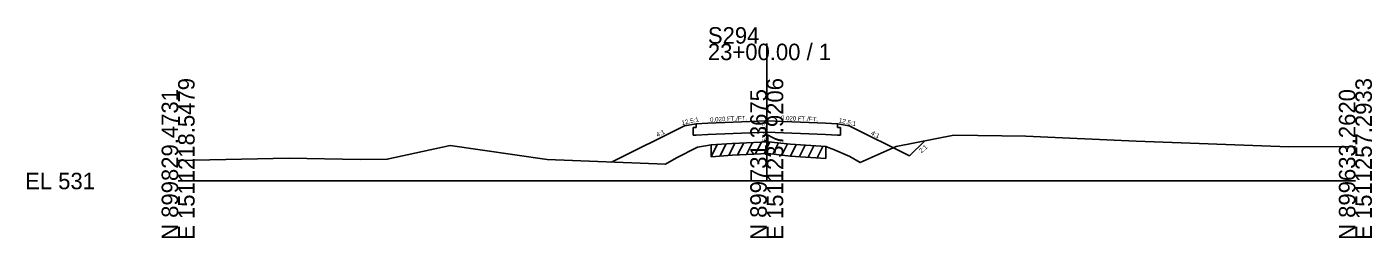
# Model space of a CAD drawing. Extents: x 974 to 2203, y -10 to 19041.
# Drawn here: x 1974.3 to 2202.8, y 5990.3 to 6026.2 of the extents above; entities that cross this region are included whole.
import ezdxf

# ---------------------------------------------------------------- set-up
doc = ezdxf.new("R2010")
doc.units = 0
for name, color, linetype in [('RD_GPK_XS_Cell', 7, 'Continuous'), ('RD_XS_Base', 7, 'Continuous'), ('RD_XS_EarthShd', 7, 'Continuous'), ('RD_XS_ExGround', 7, 'Continuous'), ('RD_XS_ExPaveRet', 7, 'Continuous'), ('RD_XS_Pave', 7, 'Continuous'), ('RD_XS_TX_Elev_EX', 7, 'Continuous'), ('RD_XS_TX_Slope', 7, 'Continuous')]:
    doc.layers.add(name, color=color, linetype=linetype)

msp = doc.modelspace()

# ---------------------------------------------------------------- linework, layer by layer
at = {"layer": 'RD_GPK_XS_Cell'}
for p, q in [((2100, 6000), (2100, 6023.32)), ((2000, 6000), (2100, 6000)), ((2100, 6000), (2200, 6000))]:
    msp.add_line(p, q, dxfattribs=at)
at = {"layer": 'RD_XS_Base'}
for p, q in [((2088, 6009.08), (2087.48, 6009.06)), ((2087.48, 6007.79), (2087.48, 6009.06)), ((2088, 6009.08), (2088, 6009.72)), ((2090, 6007.89), (2100, 6008.29)), ((2110, 6007.89), (2100, 6008.29)), ((2112, 6009.08), (2112, 6009.72)), ((2112, 6009.08), (2112.52, 6009.06)), ((2112.52, 6007.79), (2112.52, 6009.06)), ((2087.98, 6007.81), (2087.48, 6007.79)), ((2087.98, 6007.81), (2090, 6007.89)), ((2112.02, 6007.81), (2110, 6007.89)), ((2112.02, 6007.81), (2112.52, 6007.79))]:
    msp.add_line(p, q, dxfattribs=at)
at = {"layer": 'RD_XS_EarthShd'}
for p, q in [((2086, 6009.39), (2073.6, 6003.19)), ((2088, 6009.72), (2086, 6009.39)), ((2112, 6009.72), (2114, 6009.39)), ((2114, 6009.39), (2124.26, 6004.26)), ((2124.26, 6004.26), (2126.79, 6006.79))]:
    msp.add_line(p, q, dxfattribs=at)
at = {"layer": 'RD_XS_ExGround'}
msp.add_lwpolyline([(2000, 6003.46), (2018.84, 6003.85), (2030.91, 6003.65), (2035.53, 6003.68), (2046.24, 6006.01), (2062.67, 6003.63), (2082.77, 6002.83), (2084.66, 6003.95), (2088.25, 6005.76), (2089.59, 6005.95), (2090.55, 6006.12), (2094.15, 6006.38), (2100.25, 6006.67), (2104.01, 6006.24), (2110.06, 6005.83), (2110.91, 6005.53), (2111.24, 6005.43), (2114.11, 6004.15), (2115.85, 6003.12), (2121.99, 6005.85), (2131.78, 6007.77), (2144.01, 6007.64), (2162.74, 6006.75), (2188.69, 6005.81), (2200, 6005.88)], dxfattribs=at)
at = {"layer": 'RD_XS_ExPaveRet'}
for p, q in [((2090.55, 6004.12), (2091.59, 6006.19)), ((2090.55, 6004.12), (2090.55, 6006.12)), ((2092.05, 6004.23), (2093.09, 6006.3)), ((2093.55, 6004.33), (2094.58, 6006.4)), ((2095.05, 6004.42), (2096.08, 6006.47)), ((2096.55, 6004.49), (2097.58, 6006.54)), ((2098.05, 6004.56), (2099.08, 6006.61)), ((2099.55, 6004.63), (2100.55, 6006.63)), ((2101.05, 6004.58), (2102, 6006.47)), ((2102.55, 6004.41), (2103.5, 6006.3)), ((2104.05, 6004.24), (2105.02, 6006.18)), ((2105.55, 6004.14), (2106.52, 6006.07)), ((2107.05, 6004.04), (2108.02, 6005.97)), ((2108.55, 6003.93), (2109.52, 6005.87)), ((2090.55, 6004.12), (2094.15, 6004.38)), ((2094.15, 6004.38), (2100.25, 6004.67)), ((2100.25, 6004.67), (2104.01, 6004.24)), ((2104.01, 6004.24), (2110.06, 6003.83)), ((2110.06, 6005.83), (2110.06, 6003.83))]:
    msp.add_line(p, q, dxfattribs=at)
at = {"layer": 'RD_XS_Pave'}
for p, q in [((2088, 6009.72), (2090, 6009.8)), ((2090, 6009.8), (2100, 6010.2)), ((2110, 6009.8), (2100, 6010.2)), ((2112, 6009.72), (2110, 6009.8))]:
    msp.add_line(p, q, dxfattribs=at)

# ---------------------------------------------------------------- texts
at = {"layer": 'RD_GPK_XS_Cell'}
for s, p in [('S294', (2090, 6023.32)), ('23+00.00 / 1', (2090, 6020.52)), ('EL 531', (1974, 5998.6))]:
    msp.add_text(s, height=2.8, dxfattribs=at).set_placement(p)
for s, p in [('E 1511218.5479', (2002.8, 5990)), ('E 1511237.9206', (2102.8, 5990)), ('E 1511257.2933', (2202.8, 5990)), ('N 899829.4731', (2000, 5990)), ('N 899731.3675', (2100, 5990)), ('N 899633.2620', (2200, 5990))]:
    msp.add_text(s, height=2.8, rotation=90, dxfattribs=at).set_placement(p)
at = {"layer": 'RD_XS_TX_Elev_EX'}
msp.add_text('534.33', height=0.75, rotation=90, dxfattribs=at).set_placement((2100, 6006.66))
at = {"layer": 'RD_XS_TX_Slope'}
for s, height, rotation, p in [('12.5:1', 0.778, 12.7511, (2085.61, 6009.47)), ('0.020 FT./FT.', 0.7518, 2.396, (2090.38, 6010.06)), ('0.020 FT./FT.', 0.7518, 357.604, (2102.4, 6010.36)), ('12.5:1', 0.778, 347.2489, (2112.17, 6009.97)), ('4:1', 0.778, 26.3688, (2081.44, 6007.42)), ('4:1', 0.778, 333.6312, (2117.62, 6007.89)), ('2:1', 0.778, 40.6589, (2126.26, 6004.69))]:
    msp.add_text(s, height=height, rotation=rotation, dxfattribs=at).set_placement(p)

doc.saveas('drawing.dxf')
